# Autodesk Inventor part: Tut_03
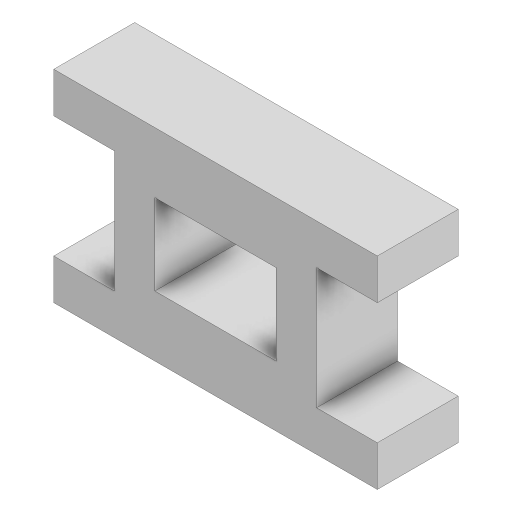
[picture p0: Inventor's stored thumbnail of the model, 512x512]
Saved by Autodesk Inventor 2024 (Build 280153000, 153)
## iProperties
Created: 2022-07
Part Number: Tut_03
Material: Generic
Document SubType Name: Modeling
Designer: LENOVO-CADCIM
Density: 1 g/cm^3
Appearance: Default
Author: LENOVO-CADCIM
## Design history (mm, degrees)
sketch "Sketch1"
  geometry: L1 (0, 0)-(40, 0); L2 (40, 0)-(40, 10); L3 (40, 10)-(25, 10); L4 (25, 10)-(25, 40); L5 (25, 40)-(40, 40); L6 (40, 40)-(40, 50); L7 (40, 50)-(-40, 50); L8 (-40, 50)-(-40, 40); L9 (-40, 40)-(-25, 40); L10 (-25, 40)-(-25, 10); L11 (-25, 10)-(-40, 10); L12 (-40, 10)-(-40, 0); L13 (-40, 0)-(0, 0); L14 (-15, 15)-(15, 15); L15 (15, 15)-(15, 35); L16 (15, 35)-(-15, 35); L17 (-15, 35)-(-15, 15)
  constraints: 34 end point, 13 perpendicular, 2 horizontal, 2 parallel, 1 collinear, 1 point on line
  dimensions: "d0" = 40 distance of L1.start L1.end; "d1" = 10 distance of L1.end L2.end; "d2" = 15 distance of L2.end L3.end; "d3" = 30 distance between parallel lines of L3 L5; "d4" = 15 distance of L4.end L5.end; "d5" = 10 distance of L5.end L6.end; "d6" = 10 distance of L7.end L8.end; "d7" = 15 distance of L8.end L9.end; "d8" = 30 distance of L9.end L10.end; "d9" = 15 distance of L10.end L11.end; "d11" = 20 distance of L16.end L14.start; "d12" = 30 distance of L14.start L14.end; "d13" = 10 distance between parallel lines of L4 L15; "d14" = 15 distance between parallel lines of L14 L1
extrude "Extrusion1" new body sketch "Sketch1" distance "d15" = 20; taper "d16" = 0 deg
body "Solid1"
